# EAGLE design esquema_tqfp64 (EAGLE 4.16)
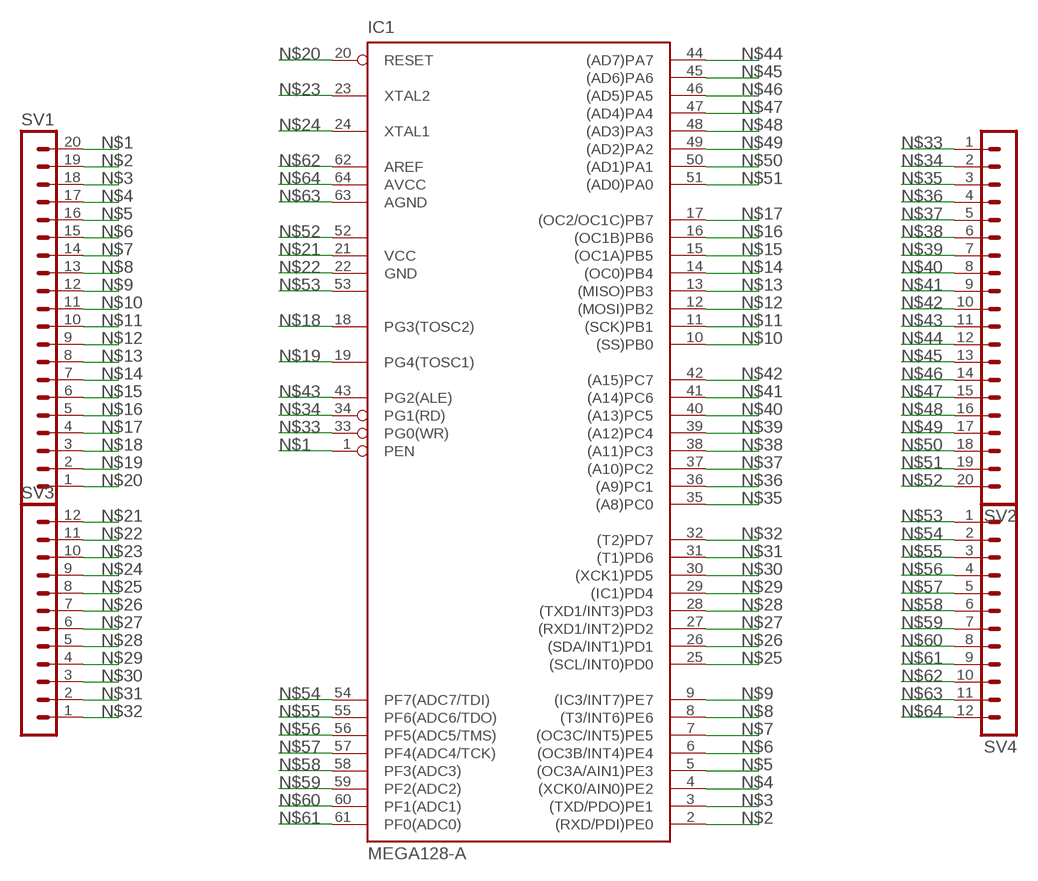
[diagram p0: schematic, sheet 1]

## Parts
IC1  MEGA128-A  [TQFP64]
SV1  MA20-1  [MA20-1]
SV2  MA20-1  [MA20-1]
SV3  MA12-1  [MA12-1]
SV4  MA12-1  [MA12-1]

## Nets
N$1: IC1.1(PEN) SV1.20
N$2: IC1.2((RXD/PDI)PE0) SV1.19
N$3: IC1.3((TXD/PDO)PE1) SV1.18
N$4: IC1.4((XCK0/AIN0)PE2) SV1.17
N$5: IC1.5((OC3A/AIN1)PE3) SV1.16
N$6: IC1.6((OC3B/INT4)PE4) SV1.15
N$7: IC1.7((OC3C/INT5)PE5) SV1.14
N$8: IC1.8((T3/INT6)PE6) SV1.13
N$9: IC1.9((IC3/INT7)PE7) SV1.12
N$10: IC1.10((SS)PB0) SV1.11
N$11: IC1.11((SCK)PB1) SV1.10
N$12: IC1.12((MOSI)PB2) SV1.9
N$13: IC1.13((MISO)PB3) SV1.8
N$14: IC1.14((OC0)PB4) SV1.7
N$15: IC1.15((OC1A)PB5) SV1.6
N$16: IC1.16((OC1B)PB6) SV1.5
N$17: IC1.17((OC2/OC1C)PB7) SV1.4
N$18: IC1.18(PG3(TOSC2)) SV1.3
N$19: IC1.19(PG4(TOSC1)) SV1.2
N$20: IC1.20(RESET) SV1.1
N$21: IC1.21(VCC) SV3.12
N$22: IC1.22(GND) SV3.11
N$23: IC1.23(XTAL2) SV3.10
N$24: IC1.24(XTAL1) SV3.9
N$25: IC1.25((SCL/INT0)PD0) SV3.8
N$26: IC1.26((SDA/INT1)PD1) SV3.7
N$27: IC1.27((RXD1/INT2)PD2) SV3.6
N$28: IC1.28((TXD1/INT3)PD3) SV3.5
N$29: IC1.29((IC1)PD4) SV3.4
N$30: IC1.30((XCK1)PD5) SV3.3
N$31: IC1.31((T1)PD6) SV3.2
N$32: IC1.32((T2)PD7) SV3.1
N$33: IC1.33(PG0(WR)) SV2.1
N$34: IC1.34(PG1(RD)) SV2.2
N$35: IC1.35((A8)PC0) SV2.3
N$36: IC1.36((A9)PC1) SV2.4
N$37: IC1.37((A10)PC2) SV2.5
N$38: IC1.38((A11)PC3) SV2.6
N$39: IC1.39((A12)PC4) SV2.7
N$40: IC1.40((A13)PC5) SV2.8
N$41: IC1.41((A14)PC6) SV2.9
N$42: IC1.42((A15)PC7) SV2.10
N$43: IC1.43(PG2(ALE)) SV2.11
N$44: IC1.44((AD7)PA7) SV2.12
N$45: IC1.45((AD6)PA6) SV2.13
N$46: IC1.46((AD5)PA5) SV2.14
N$47: IC1.47((AD4)PA4) SV2.15
N$48: IC1.48((AD3)PA3) SV2.16
N$49: IC1.49((AD2)PA2) SV2.17
N$50: IC1.50((AD1)PA1) SV2.18
N$51: IC1.51((AD0)PA0) SV2.19
N$52: IC1.52(VCC1) SV2.20
N$53: IC1.53(GND1) SV4.1
N$54: IC1.54(PF7(ADC7/TDI)) SV4.2
N$55: IC1.55(PF6(ADC6/TDO)) SV4.3
N$56: IC1.56(PF5(ADC5/TMS)) SV4.4
N$57: IC1.57(PF4(ADC4/TCK)) SV4.5
N$58: IC1.58(PF3(ADC3)) SV4.6
N$59: IC1.59(PF2(ADC2)) SV4.7
N$60: IC1.60(PF1(ADC1)) SV4.8
N$61: IC1.61(PF0(ADC0)) SV4.9
N$62: IC1.62(AREF) SV4.10
N$63: IC1.63(AGND) SV4.11
N$64: IC1.64(AVCC) SV4.12

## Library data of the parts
IC1 = atmel:MEGA128: MICROCONTROLLER 128 Kbytes FLASH 4 Kbytes SRAM 4 Kbytes EEPROM DUAL USART 8-channel 10 bit ADC Source: avr.lbr
SV1 SV2 = con-lstb:MA20-1: PIN HEADER
SV3 SV4 = con-lstb:MA12-1: PIN HEADER

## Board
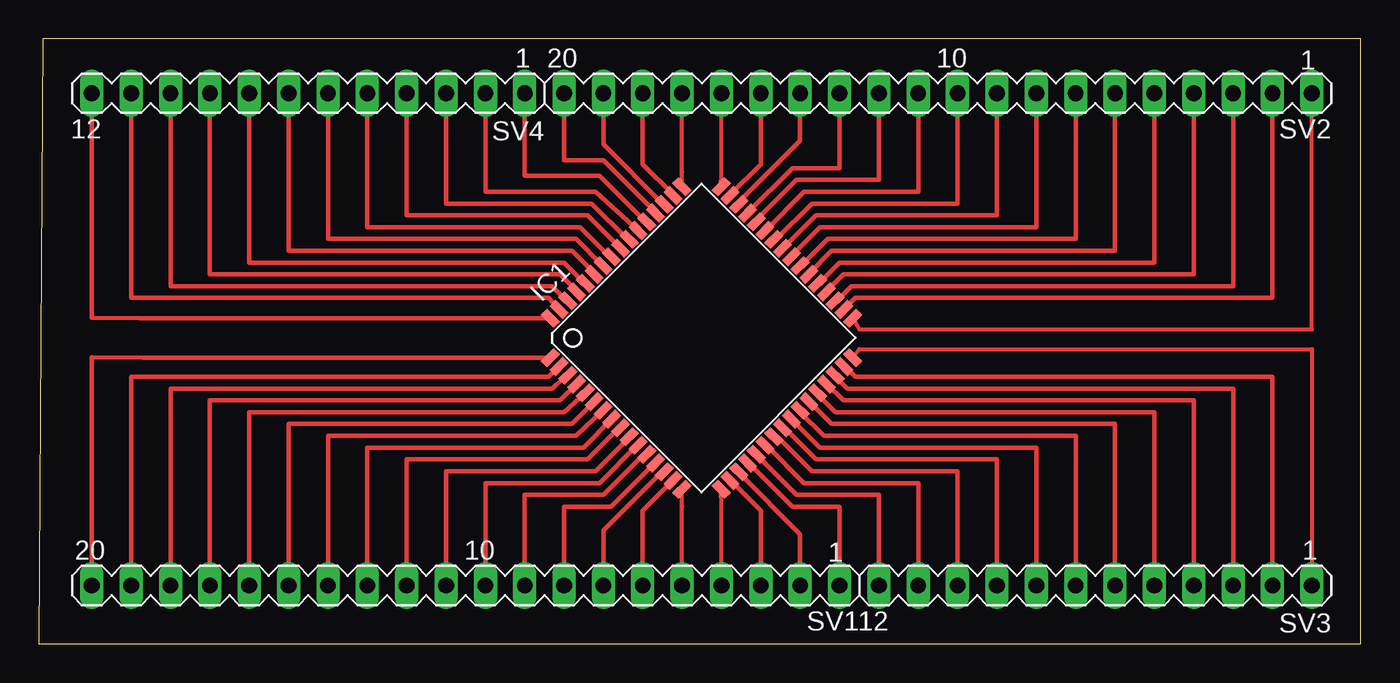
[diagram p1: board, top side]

Size 85.32 x 39.04 mm. Coordinates in mm from the lower left corner, seen from the top.
Outline: 0,0 85.32,0 85.32,39.04 0.25,39.04 0,0
Copper layers (1*16): Top 0.035mm / dielectric 1.5mm / Bottom 0.035mm
Design rules "default": minimum track width 10mil, minimum drill 24mil, track to track 8mil, track to pad 8mil, pad to pad 8mil, via to via 8mil, smd to smd 8mil, copper to edge 40mil, drill to drill 8mil, minimum pad ring 10mil, minimum via ring 8mil, stop-mask expansion 4mil, vias tented up to drill 0mil, thermal gap 10mil

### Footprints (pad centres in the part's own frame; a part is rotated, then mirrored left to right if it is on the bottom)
TQFP64 = smd 1.194 x 0.559: 1 -7.8,6; 2 -7.8,5.2; 3 -7.8,4.4; 4 -7.8,3.6; 5 -7.8,2.8; 6 -7.8,2; 7 -7.8,1.2; 8 -7.8,0.4; 9 -7.8,-0.4; 10 -7.8,-1.2; 11 -7.8,-2; 12 -7.8,-2.8; 13 -7.8,-3.6; 14 -7.8,-4.4; 15 -7.8,-5.2; 16 -7.8,-6; 33 7.8,-6; 34 7.8,-5.2; 35 7.8,-4.4; 36 7.8,-3.6; 37 7.8,-2.8; 38 7.8,-2; 39 7.8,-1.2; 40 7.8,-0.4; 41 7.8,0.4; 42 7.8,1.2; 43 7.8,2; 44 7.8,2.8; 45 7.8,3.6; 46 7.8,4.4; 47 7.8,5.2; 48 7.8,6 | smd 0.559 x 1.194: 17 -6,-7.8; 18 -5.2,-7.8; 19 -4.4,-7.8; 20 -3.6,-7.8; 21 -2.8,-7.8; 22 -2,-7.8; 23 -1.2,-7.8; 24 -0.4,-7.8; 25 0.4,-7.8; 26 1.2,-7.8; 27 2,-7.8; 28 2.8,-7.8; 29 3.6,-7.8; 30 4.4,-7.8; 31 5.2,-7.8; 32 6,-7.8; 49 6,7.8; 50 5.2,7.8; 51 4.4,7.8; 52 3.6,7.8; 53 2.8,7.8; 54 2,7.8; 55 1.2,7.8; 56 0.4,7.8; 57 -0.4,7.8; 58 -1.2,7.8; 59 -2,7.8; 60 -2.8,7.8; 61 -3.6,7.8; 62 -4.4,7.8; 63 -5.2,7.8; 64 -6,7.8
MA20-1 = drill 1.016 long: 1 -24.13,0; 2 -21.59,0; 3 -19.05,0; 4 -16.51,0; 5 -13.97,0; 6 -11.43,0; 7 -8.89,0; 8 -6.35,0; 9 -3.81,0; 10 -1.27,0; 11 1.27,0; 12 3.81,0; 13 6.35,0; 14 8.89,0; 15 11.43,0; 16 13.97,0; 17 16.51,0; 18 19.05,0; 19 21.59,0; 20 24.13,0
MA12-1 = drill 1.016 long: 1 -13.97,0; 2 -11.43,0; 3 -8.89,0; 4 -6.35,0; 5 -3.81,0; 6 -1.27,0; 7 1.27,0; 8 3.81,0; 9 6.35,0; 10 8.89,0; 11 11.43,0; 12 13.97,0

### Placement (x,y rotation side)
IC1  42.78,19.73 45 top
SV1  27.55,3.77 180 top
SV2  58.03,35.52 180 top
SV3  68.19,3.77 180 top
SV4  17.39,35.52 180 top

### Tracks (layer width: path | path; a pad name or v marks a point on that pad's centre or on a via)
N$1
  Top 0.305: IC1.1 6.73,18.46 3.42,18.5 SV1.20
N$2
  Top 0.305: IC1.2 32.89,17.23 5.96,17.23 SV1.19
N$3
  Top 0.305: IC1.3 33.4,16.73 33.14,16.47 8.5,16.47 SV1.18
N$4
  Top 0.305: IC1.4 33.65,15.71 11.04,15.71 SV1.17
N$5
  Top 0.305: IC1.5 33.9,14.95 13.58,14.95 SV1.16
N$6
  Top 0.305: IC1.6 34.41,14.19 16.12,14.19 SV1.15
N$7
  Top 0.305: IC1.7 34.67,13.42 18.66,13.42 SV1.14
N$8
  Top 0.305: IC1.8 35.17,12.66 21.2,12.66 SV1.13
N$9
  Top 0.305: IC1.9 37.46,13.94 35.43,11.9 23.74,11.9 SV1.12
N$10
  Top 0.305: IC1.10 38.11,13.31 35.94,11.14 26.28,11.14 SV1.11
N$11
  Top 0.305: IC1.11 38.62,12.8 36.19,10.38 28.82,10.38 SV1.10
N$12
  Top 0.305: IC1.12 39.07,12.24 36.44,9.61 31.36,9.61 SV1.9
N$13
  Top 0.305: IC1.13 39.77,11.67 36.95,8.85 33.9,8.85 SV1.8
N$14
  Top 0.305: IC1.14 40.22,11.11 36.44,7.33 SV1.7
N$15
  Top 0.305: IC1.15 38.98,8.6 SV1.6
N$16
  Top 0.254: IC1.16 41.52,8.85 SV1.5
N$17
  Top 0.254: IC1.17 44.06,8.85 SV1.4
N$18
  Top 0.305: IC1.18 44.66,10.54 46.6,8.6 SV1.3
N$19
  Top 0.305: IC1.19 45.18,11.04 49.14,7.07 SV1.2
N$20
  Top 0.305: IC1.20 45.81,11.67 48.64,8.85 51.68,8.85 SV1.1
N$21
  Top 0.305: IC1.21 46.31,12.19 48.89,9.61 54.22,9.61 SV3.12
N$22
  Top 0.305: IC1.22 46.97,12.8 49.4,10.38 56.76,10.38 SV3.11
N$23
  Top 0.305: IC1.23 47.67,13.37 49.91,11.14 59.3,11.14 SV3.10
N$24
  Top 0.305: IC1.24 48.12,13.94 50.16,11.9 61.84,11.9 SV3.9
N$25
  Top 0.305: IC1.25 50.41,12.66 64.38,12.66 SV3.8
N$26
  Top 0.305: IC1.26 49.14,14.95 50.67,13.42 66.92,13.42 SV3.7
N$27
  Top 0.305: IC1.27 49.73,15.63 51.18,14.19 69.46,14.19 SV3.6
N$28
  Top 0.305: IC1.28 50.27,16.11 51.43,14.95 72,14.95 SV3.5
N$29
  Top 0.305: IC1.29 50.88,16.77 51.94,15.71 74.54,15.71 SV3.4
N$30
  Top 0.305: IC1.30 51.4,17.26 52.19,16.47 77.08,16.47 SV3.3
N$31
  Top 0.305: IC1.31 52.04,17.9 52.7,17.23 79.62,17.23 SV3.2
N$32
  Top 0.254: IC1.32 52.95,19.01 82.16,19.01 SV3.1
N$33
  Top 0.254: IC1.33 52.95,20.28 82.16,20.28 SV2.1
N$34
  Top 0.305: IC1.34 52.7,22.31 79.62,22.31 SV2.2
N$35
  Top 0.305: IC1.35 51.51,22.14 52.45,23.08 77.08,23.08 SV2.3
N$36
  Top 0.305: IC1.36 50.8,22.7 51.94,23.84 74.54,23.84 SV2.4
N$37
  Top 0.305: IC1.37 50.35,23.27 51.68,24.6 72,24.6 SV2.5
N$38
  Top 0.305: IC1.38 49.7,23.89 51.18,25.36 69.46,25.36 SV2.6
N$39
  Top 0.305: IC1.39 49.2,24.4 50.92,26.12 66.92,26.12 SV2.7
N$40
  Top 0.305: IC1.40 48.57,25.05 50.41,26.89 64.38,26.89 SV2.8
N$41
  Top 0.305: IC1.41 48.05,25.53 50.16,27.65 61.84,27.65 SV2.9
N$42
  Top 0.305: IC1.42 47.59,26.1 49.91,28.41 59.3,28.41 SV2.10
N$43
  Top 0.305: IC1.43 46.89,26.66 49.4,29.17 56.76,29.17 SV2.11
N$44
  Top 0.305: IC1.44 46.31,27.35 48.89,29.93 54.22,29.93 SV2.12
N$45
  Top 0.305: IC1.45 45.74,27.8 48.64,30.7 51.68,30.7 SV2.13
N$46
  Top 0.305: IC1.46 45.18,28.51 49.14,32.47 SV2.14
N$47
  Top 0.305: IC1.47 44.61,28.96 46.6,30.95 SV2.15
N$48
  Top 0.254: IC1.48 44.06,30.44 SV2.16
N$49
  Top 0.254: IC1.49 41.52,30.44 SV2.17
N$50
  Top 0.305: IC1.50 40.94,29 38.98,30.95 SV2.18
N$51
  Top 0.305: IC1.51 40.3,28.36 36.44,32.22 SV2.19
N$52
  Top 0.305: IC1.52 39.81,27.84 36.44,31.2 33.9,31.2 SV2.20
N$53
  Top 0.305: IC1.53 39.15,27.23 36.19,30.19 31.36,30.19 SV4.1
N$54
  Top 0.305: IC1.54 38.7,26.66 35.94,29.17 28.82,29.17 SV4.2
N$55
  Top 0.305: IC1.55 37.99,26.1 35.68,28.41 26.28,28.41 SV4.3
N$56
  Top 0.305: IC1.56 | IC1.56 35.43,27.65 23.74,27.65 SV4.4
N$57
  Top 0.305: IC1.57 36.84,24.97 34.92,26.89 21.2,26.89 SV4.5
N$58
  Top 0.305: IC1.58 36.39,24.4 34.67,26.12 18.66,26.12 SV4.6
N$59
  Top 0.305: IC1.59 35.85,23.93 34.41,25.36 16.12,25.36 SV4.7
N$60
  Top 0.305: IC1.60 35.23,23.27 33.9,24.6 13.58,24.6 SV4.8
N$61
  Top 0.305: IC1.61 34.72,22.77 33.65,23.84 11.04,23.84 SV4.9
N$62
  Top 0.305: IC1.62 34.08,22.14 33.14,23.08 8.5,23.08 SV4.10
N$63
  Top 0.305: IC1.63 32.89,22.31 5.96,22.31 SV4.11
N$64
  Top 0.305: IC1.64 6.47,21.01 3.42,21.04 SV4.12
